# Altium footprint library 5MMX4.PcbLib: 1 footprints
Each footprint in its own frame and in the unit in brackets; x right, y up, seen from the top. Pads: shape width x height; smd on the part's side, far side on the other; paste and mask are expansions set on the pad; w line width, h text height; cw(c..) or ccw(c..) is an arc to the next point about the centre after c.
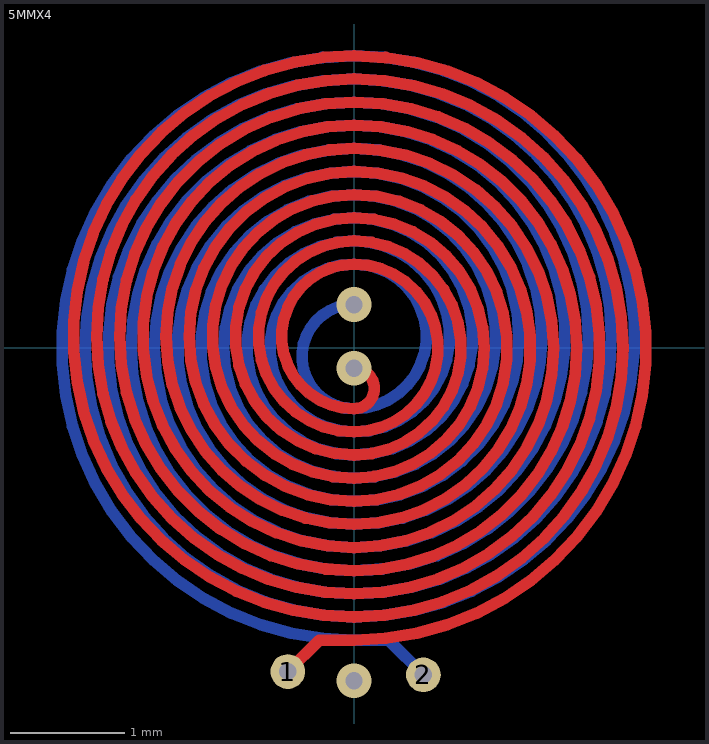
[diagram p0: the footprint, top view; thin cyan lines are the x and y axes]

## 5MMX4 [mil] "4MIL,4MIL,50MIL,12MIL,6MIL,10T"
pads (2):
  round 12 hole 6: 1(-22.87,-111.87) 2(24,-113)
via 0,15 diameter 12 hole 6
via 0,-7 diameter 12 hole 6
via 0,-115 diameter 12 hole 6
Top Layer:
  lines w4: -12,-101 -22.87,-111.87 -12,-101 ; -12,-101 0,-101 ; -12,-101 0,-101 ; 0,-101 ccw(c0,0) 0,101 ; 0,-101 ccw(c0,0) 0,101 ; 0,-101 0,-101 ; 0,-93 ccw(c0,0) 0,93 ; 0,-93 cw(c0,4) 0,101 ; 0,-93 cw(c0,4) 0,101 ; 0,-93 ccw(c0,0) 0,93 ; 0,-85 ccw(c0,0) 0,85 ; 0,-85 cw(c0,4) 0,93 ; 0,-85 cw(c0,4) 0,93 ; 0,-85 ccw(c0,0) 0,85 ; 0,-77 ccw(c0,0) 0,77 ; 0,-77 cw(c0,4) 0,85 ; 0,-77 cw(c0,4) 0,85 ; 0,-77 ccw(c0,0) 0,77 ; 0,-69 ccw(c0,0) 0,69 ; 0,-69 cw(c0,4) 0,77 ; 0,-69 cw(c0,4) 0,77 ; 0,-69 ccw(c0,0) 0,69 ; 0,-61 ccw(c0,0) 0,61 ; 0,-61 cw(c0,4) 0,69 ; 0,-61 cw(c0,4) 0,69 ; 0,-61 ccw(c0,0) 0,61 ; 0,-53 ccw(c0,0) 0,53 ; 0,-53 cw(c0,4) 0,61 ; 0,-53 cw(c0,4) 0,61 ; 0,-53 ccw(c0,0) 0,53 ; 0,-45 ccw(c0,0) 0,45 ; 0,-45 cw(c0,4) 0,53 ; 0,-45 cw(c0,4) 0,53 ; 0,-45 ccw(c0,0) 0,45 ; 0,-37 ccw(c0,0) 0,37 ; 0,-37 cw(c0,4) 0,45 ; 0,-37 cw(c0,4) 0,45 ; 0,-37 ccw(c0,0) 0,37 ; 0,-29 ccw(c0,0) 0,29 ; 0,-29 cw(c0,4) 0,37 ; 0,-29 cw(c0,4) 0,37 ; 0,-29 ccw(c0,0) 0,29 ; 0,-21 ccw(c0,-14) 0,-7 cw(c0,-14) 0,-21 ; 0,-21 cw(c0,4) 0,29 ; 0,-21 cw(c0,4) 0,29
Mid-Layer 1:
  lines w4: 0,-116 0,-101 ; 0,-115 0,-101 ; 0,-101 cw(c0,0) 0,101 ; 0,-101 cw(c0,0) 0,101 ; 0,-93 ccw(c0,4) 0,101 ; 0,-93 cw(c0,0) 0,93 ; 0,-93 cw(c0,0) 0,93 ; 0,-93 ccw(c0,4) 0,101 ; 0,-85 ccw(c0,4) 0,93 ; 0,-85 cw(c0,0) 0,85 ; 0,-85 cw(c0,0) 0,85 ; 0,-85 ccw(c0,4) 0,93 ; 0,-77 ccw(c0,4) 0,85 ; 0,-77 cw(c0,0) 0,77 ; 0,-77 cw(c0,0) 0,77 ; 0,-77 ccw(c0,4) 0,85 ; 0,-69 ccw(c0,4) 0,77 ; 0,-69 cw(c0,0) 0,69 ; 0,-69 cw(c0,0) 0,69 ; 0,-69 ccw(c0,4) 0,77 ; 0,-61 ccw(c0,4) 0,69 ; 0,-61 cw(c0,0) 0,61 ; 0,-61 cw(c0,0) 0,61 ; 0,-61 ccw(c0,4) 0,69 ; 0,-53 ccw(c0,4) 0,61 ; 0,-53 cw(c0,0) 0,53 ; 0,-53 cw(c0,0) 0,53 ; 0,-53 ccw(c0,4) 0,61 ; 0,-45 ccw(c0,4) 0,53 ; 0,-45 cw(c0,0) 0,45 ; 0,-45 cw(c0,0) 0,45 ; 0,-45 ccw(c0,4) 0,53 ; 0,-37 ccw(c0,4) 0,45 ; 0,-37 cw(c0,0) 0,37 ; 0,-37 cw(c0,0) 0,37 ; 0,-37 ccw(c0,4) 0,45 ; 0,-29 ccw(c0,4) 0,37 ; 0,-29 cw(c0,0) 0,29 ; 0,-29 cw(c0,0) 0,29 ; 0,-29 ccw(c0,4) 0,37 ; 0,-21 ccw(c0,4) 0,29 ; 0,-21 cw(c0,-14) 0,-7 ccw(c0,-14) 0,-21 ; 0,-21 ccw(c0,4) 0,29
Mid-Layer 2:
  lines w4: 0,-116 0,-101 ; 0,-115 0,-101 ; 0,-101 ccw(c0,0) 0,101 ; 0,-101 ccw(c0,0) 0,101 ; 0,-93 ccw(c0,0) 0,93 ; 0,-93 cw(c0,4) 0,101 ; 0,-93 cw(c0,4) 0,101 ; 0,-93 ccw(c0,0) 0,93 ; 0,-85 ccw(c0,0) 0,85 ; 0,-85 cw(c0,4) 0,93 ; 0,-85 cw(c0,4) 0,93 ; 0,-85 ccw(c0,0) 0,85 ; 0,-77 ccw(c0,0) 0,77 ; 0,-77 cw(c0,4) 0,85 ; 0,-77 cw(c0,4) 0,85 ; 0,-77 ccw(c0,0) 0,77 ; 0,-69 ccw(c0,0) 0,69 ; 0,-69 cw(c0,4) 0,77 ; 0,-69 cw(c0,4) 0,77 ; 0,-69 ccw(c0,0) 0,69 ; 0,-61 ccw(c0,0) 0,61 ; 0,-61 cw(c0,4) 0,69 ; 0,-61 cw(c0,4) 0,69 ; 0,-61 ccw(c0,0) 0,61 ; 0,-53 ccw(c0,0) 0,53 ; 0,-53 cw(c0,4) 0,61 ; 0,-53 cw(c0,4) 0,61 ; 0,-53 ccw(c0,0) 0,53 ; 0,-45 ccw(c0,0) 0,45 ; 0,-45 cw(c0,4) 0,53 ; 0,-45 cw(c0,4) 0,53 ; 0,-45 ccw(c0,0) 0,45 ; 0,-37 ccw(c0,0) 0,37 ; 0,-37 cw(c0,4) 0,45 ; 0,-37 cw(c0,4) 0,45 ; 0,-37 ccw(c0,0) 0,37 ; 0,-29 ccw(c0,0) 0,29 ; 0,-29 cw(c0,4) 0,37 ; 0,-29 cw(c0,4) 0,37 ; 0,-29 ccw(c0,0) 0,29 ; 0,-21 ccw(c0,-3) 0,15 cw(c0,-3) 0,-21 ; 0,-21 cw(c0,4) 0,29 ; 0,-21 cw(c0,4) 0,29
Bottom Layer:
  lines w4: 24,-113 12,-101 ; 0,-101 cw(c0,0) 0,101 ; 0,-101 cw(c0,0) 0,101 ; 0,-101 12,-101 ; 0,-101 0,-101 ; 0,-101 12,-101 ; 0,-93 ccw(c0,4) 0,101 ; 0,-93 cw(c0,0) 0,93 ; 0,-93 cw(c0,0) 0,93 ; 0,-93 ccw(c0,4) 0,101 ; 0,-85 ccw(c0,4) 0,93 ; 0,-85 cw(c0,0) 0,85 ; 0,-85 cw(c0,0) 0,85 ; 0,-85 ccw(c0,4) 0,93 ; 0,-77 ccw(c0,4) 0,85 ; 0,-77 cw(c0,0) 0,77 ; 0,-77 cw(c0,0) 0,77 ; 0,-77 ccw(c0,4) 0,85 ; 0,-69 ccw(c0,4) 0,77 ; 0,-69 cw(c0,0) 0,69 ; 0,-69 cw(c0,0) 0,69 ; 0,-69 ccw(c0,4) 0,77 ; 0,-61 ccw(c0,4) 0,69 ; 0,-61 cw(c0,0) 0,61 ; 0,-61 cw(c0,0) 0,61 ; 0,-61 ccw(c0,4) 0,69 ; 0,-53 ccw(c0,4) 0,61 ; 0,-53 cw(c0,0) 0,53 ; 0,-53 cw(c0,0) 0,53 ; 0,-53 ccw(c0,4) 0,61 ; 0,-45 ccw(c0,4) 0,53 ; 0,-45 cw(c0,0) 0,45 ; 0,-45 cw(c0,0) 0,45 ; 0,-45 ccw(c0,4) 0,53 ; 0,-37 ccw(c0,4) 0,45 ; 0,-37 cw(c0,0) 0,37 ; 0,-37 cw(c0,0) 0,37 ; 0,-37 ccw(c0,4) 0,45 ; 0,-29 ccw(c0,4) 0,37 ; 0,-29 cw(c0,0) 0,29 ; 0,-29 cw(c0,0) 0,29 ; 0,-29 ccw(c0,4) 0,37 ; 0,-21 ccw(c0,4) 0,29 ; 0,-21 cw(c0,-3) 0,15 ccw(c0,-3) 0,-21 ; 0,-21 ccw(c0,4) 0,29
